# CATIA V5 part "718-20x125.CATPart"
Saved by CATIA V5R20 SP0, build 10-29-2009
Part number: 718-20x125
Definition: NONE
Nomenclature: 718-20x125
Source: Unknown
Description: 718-20x125
Bounding box of the stored display mesh (mm): x 0 to 148, y -12.5 to 12.5, z -12.5 to 12.5
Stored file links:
  C:\Users\Utente\Desktop\IO LAVORO\3D X SITO CF\X SITO\718\718-20x125.CATPart

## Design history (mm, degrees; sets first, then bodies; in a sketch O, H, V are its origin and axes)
Body1 "718-20x125" (main body)
  Solid1: solid without history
